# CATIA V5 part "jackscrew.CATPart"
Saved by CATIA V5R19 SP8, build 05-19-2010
Part number: jackscrew
Bounding box of the stored display mesh (mm): x 9.425 to 60.979, y 107.6 to 142.1, z -25.103 to 2.028
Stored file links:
  G:\EU_thinkMotion\CFAO_2010\MMS_groupe1\MMS_groupe1\A reprendre\gduval\CFAO kinematic ok\jackscrew.CATPart
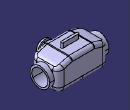
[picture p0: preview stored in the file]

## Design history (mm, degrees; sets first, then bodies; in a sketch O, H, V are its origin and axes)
Body1 (main body)
  Plane1 to Plane3: stored without definition
  Point1: stored without definition
  Line1: type Normal, RefPoint Point1, RefSkin Plane1, Start -20, End 20
  Point2: stored without definition
  Point3: stored without definition
  Line2: type PtPt, FirstPoint Point3, SecondPoint Point2
  Sketch1 on Plane1, origin (0, 118.1, 0), H (-1, 0, 0), V (0, 0, 1)
    line L1 (-35.202, -1.9724) -> (-45.1706, -1.9724)
    point P1 (-35.202, -1.9724)
    point P2 (-45.1706, -1.9724)
    line L2 (-35.202, -25.1031) -> (-56.9785, -25.1031)
    point P3 (-35.202, -25.1031)
    point P4 (-56.9785, -25.1031)
    line L3 (-56.9785, -25.1031) -> (-56.9785, -6.7308)
    point P5 (-56.9785, -6.7308)
    spline S1 through (-56.9785, -6.7308) (-54.7874, -5.0916) (-50.042, -3.334) (-45.1706, -1.9724)
    axis line L4 (-35.202, -20.106) -> (-35.202, 12.7693)
    reference projected point E1 (-35.202, -16.01) from Line1
    point P8 (-25.2334, -1.9724)
    point P9 (-35.202, -1.9724)
    line L5 (-35.202, -1.9724) -> (-25.2334, -1.9724)
    spline S2 through (-13.4255, -6.7308) (-15.6166, -5.0916) (-20.362, -3.334) (-25.2334, -1.9724)
    point P10 (-13.4255, -6.7308)
    point P11 (-13.4255, -25.1031)
    line L6 (-13.4255, -25.1031) -> (-13.4255, -6.7308)
    point P12 (-35.202, -25.1031)
    line L7 (-35.202, -25.1031) -> (-13.4255, -25.1031)
    point P13 (-56.9785, -6.7308)
    point P14 (-45.1706, -1.9724)
    point P15 (-25.2334, -1.9724)
    point P16 (-13.4255, -6.7308)
    point P17 (-50.042, -3.334)
    point P18 (-20.362, -3.334)
    point P19 (-54.7874, -5.0916)
    point P20 (-15.6166, -5.0916)
    horizontal: L1 H, L2 H
    vertical: L3 V, L4 V
    coincidence: P13 P5, P14 P2, L4 E1, P1 L4, P3 L4, P1 P9, P3 P12, P8 P15, P16 P10
    symmetry: P2 P8 L4, P1 P9 L4, L1 L5 L4, S1 S2 L4, P5 P10 L4, P4 P11 L4, L3 L6 L4, P3 P12 L4, L2 L7 L4, P14 P15 L4, P13 P16 L4, P17 P18 L4, P19 P20 L4
  Pad1: profile Sketch1, direction (0, 1, 0), up to Plane3
  Fillet1: radius 5, on edge [start face of Pad1 | face of Pad1 from Sketch1.L2]; edge [start face of Pad1 | face of Pad1 from Sketch1.L7]; edge [end face of Pad1 | face of Pad1 from Sketch1.L2]; edge [face of Pad1 from Sketch1.L6 | face of Pad1 from Sketch1.L7]; edge [end face of Pad1 | face of Pad1 from Sketch1.L7]; edge [end face of Pad1 | face of Pad1 from Sketch1.L3]; edge [face of Pad1 from Sketch1.L2 | face of Pad1 from Sketch1.L3]; edge [start face of Pad1 | face of Pad1 from Sketch1.L3]; edge [start face of Pad1 | face of Pad1 from Sketch1.L6]; edge [face of Pad1 from Sketch1.L6 | end face of Pad1]
  Fillet2: radius 3, on edge [face of Pad1 from Sketch1.S1 | face of Pad1 from Sketch1.L1]; edge [face of Pad1 from Sketch1.L5 | face of Pad1 from Sketch1.S2]
  Fillet3: radius 3, on edge [start face of Pad1 | face of Pad1 from Sketch1.S1]; edge [face of Pad1 from Sketch1.S1 | face of Fillet1] (x2); edge [face of Pad1 from Sketch1.L3 | face of Pad1 from Sketch1.S1]; edge [end face of Pad1 | face of Pad1 from Sketch1.S1]; edge [face of Pad1 from Sketch1.L1 | end face of Pad1]; edge [face of Pad1 from Sketch1.L5 | end face of Pad1]; edge [face of Pad1 from Sketch1.S2 | end face of Pad1]; edge [start face of Pad1 | face of Pad1 from Sketch1.L1]; edge [start face of Pad1 | face of Pad1 from Sketch1.L5]; edge [start face of Pad1 | face of Pad1 from Sketch1.S2]; edge [face of Pad1 from Sketch1.S2 | face of Fillet1] (x2); edge [face of Pad1 from Sketch1.S2 | face of Pad1 from Sketch1.L6]; edge [end face of Pad1 | face of Fillet2] (x2); edge [start face of Pad1 | face of Fillet2] (x2)
  Sketch2 on start face of Pad1, origin (0, 118.1, 0), H (1, 0, 0), V (0, 0, 1)
    circle A1 centre (35.202, -16.01) radius 6.5
    point P1 (35.202, -16.01)
    reference projected point E1 (35.202, -16.01) from Line1
    radius A1 = 6.5
    coincidence: P1 E1
  Pad2: profile Sketch2, direction (0, -1, 0), length 10.5
  Plane4: type Angle, RefPlane xy-plane, Direction Line1, Angle 0
  Sketch3 on Plane4, origin (0, 0, -16.01), H (1, 0, 0), V (0, 1, 0)
    line L1 (28.702, 111.1) -> (30.202, 111.1)
    line L2 (30.202, 111.1) -> (30.202, 109.1)
    line L3 (30.202, 109.1) -> (28.702, 109.1)
    line L4 (28.702, 109.1) -> (28.702, 111.1)
    reference projected line E1 (35.202, 98.1) -> (35.202, 138.1) from Line1
    reference intersected line E2 (41.702, 107.6) -> (28.702, 107.6) from end face of Pad2
    distance E1 L4 = 6.5
    distance L1 L3 = 2
    distance E2 L3 = 1.5
    distance L2 L4 = 1.5
    horizontal: L1 H, L3 H
    vertical: L2 V, L4 V
  Groove1: profile Sketch3, axis Line1, angle 360
  Sketch4 on face of Pad1 from Sketch1.L6, origin (13.4255, 0, 0), H (0, -1, 0), V (0, 0, 1)
    circle A1 centre (-130.1, -14.68) radius 8.5
    point P1 (-130.1, -14.68)
    reference projected point E1 (-130.1, -14.68) from Line2
    radius A1 = 8.5
    coincidence: E1 P1
  Pad3: profile Sketch4, direction (-1, 0, 0), length 4, opposite side up to face of Pad1 from Sketch1.L3, offset 4
  Sketch5 on end face of Pad3, origin (9.4255, 130.1, -14.68), H (0, 1, 0), V (0, 0, -1)
    point P1 (0, 0)
    intersected point E1 (0, 0) from Line2
    coincidence: E1 P1
  Hole1: placed by Sketch5, at (9.4255, 130.1, -14.68) direction (1, 0, 0), diameter 14, through (limit type 3), threaded, thread diameter 15.4, thread depth 10, pitch 1
  Sketch6 on face of Pad1 from Sketch1.L5, origin (0, 0, -1.9724), H (1, 0, 0), V (0, 1, 0)
    point P1 (27.4328, 131.1)
    line L1 (27.4328, 131.1) -> (42.7333, 131.1)
    line L2 (42.7333, 131.1) -> (42.7333, 130.1)
    line L3 (27.4328, 130.1) -> (27.4328, 131.1)
    point P2 (42.7333, 131.1)
    point P3 (42.7333, 130.1)
    point P4 (27.4328, 130.1)
    reference projected line E1 (-18.581, 130.1) -> (136.206, 130.1) from Line2
    reference projected line E2 (-18.581, 130.1) -> (136.206, 130.1) from Line2
    reference projected line E3 (-18.581, 130.1) -> (136.206, 130.1) from edge of Line2
    point P7 (42.7333, 129.1)
    point P8 (27.4328, 129.1)
    line L4 (27.4328, 129.1) -> (42.7333, 129.1)
    point P9 (42.7333, 130.1)
    line L5 (42.7333, 129.1) -> (42.7333, 130.1)
    point P10 (27.4328, 130.1)
    line L6 (27.4328, 130.1) -> (27.4328, 129.1)
    distance L1 L4 = 2
    horizontal: L1 H
    vertical: L2 V, L3 V
    coincidence: P3 E1, P4 E2, P3 P9, P4 P10
    symmetry: P2 P7 E3, P1 P8 E3, L1 L4 E3, P3 P9 E3, L2 L5 E3, P4 P10 E3, L3 L6 E3
  Pad4: profile Sketch6, direction (0, 0, 1), length 4
  Fillet4: radius 1, on edge [face of Pad4 from Sketch6.L5 | face of Pad4 from Sketch6.L4]; edge [face of Pad4 from Sketch6.L1 | face of Pad4 from Sketch6.L2]; edge [face of Pad4 from Sketch6.L3 | face of Pad4 from Sketch6.L1]; edge [face of Pad4 from Sketch6.L4 | face of Pad4 from Sketch6.L6]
